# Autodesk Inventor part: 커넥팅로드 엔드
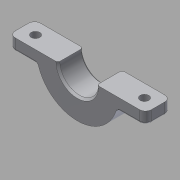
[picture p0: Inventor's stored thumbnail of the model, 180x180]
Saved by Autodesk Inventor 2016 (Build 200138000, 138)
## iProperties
Created: 2016-11
Part Number: 커넥팅로드 엔드
Material: 알루미늄 6061
Document SubType Name: Modeling
Designer: mduedu
Density: 2.71 g/cm^3
Mass: 24.1426 g
Surface Area: 36.9806 cm^2
Volume: 8.9087 cm^3
Appearance: 알루미늄 - 평지
Author: mduedu
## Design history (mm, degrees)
sketch "스케치1" dims "d0" = 42, "d3" = 20
  geometry: L1 (0, 0)-(0, 114); L2 (-7.5, 107.386)-(-12.5, 16.875); L3 (7.5, 107.386)-(12.5, 16.875); C1 r 10 at (0, 0); C2 r 6.5 at (0, 114); 3 further points
  constraints: 6 end point, 4 coincident, 2 centre point, 2 symmetric about line, 1 vertical, 6 other
  dimensions: "d1" = 20 diameter of C1; "d2" = 13 diameter of C2; "d4" = 114 distance of L1.start L1.end; "d6" = 12.5 distance from line of L1 L2.end; "d7" = 7.5 distance from line of L1 L2.start
extrude "돌출1" new body sketch "스케치1" stored distance "d8" = 13; taper "d9" = 0 deg
extrude "돌출2" join sketch "스케치1" stored distance "d10" = 20; taper "d11" = 0 deg
sketch "스케치2"
  geometry: L1 (-7.5, 107.386)-(-12.5, 16.875) reference; L2 (7.5, 107.386)-(12.5, 16.875) reference; A1 r 10 centre (0, 114) between (-7.5, 107.386) and (7.5, 107.386) reference; A2 r 21 centre (0, 0) between (-12.5, 16.875) and (12.5, 16.875) reference; 1 further point
extrude "돌출3" join sketch "스케치2" stored distance "d12" = 8; taper "d13" = 0 deg
sketch "스케치3"
  geometry: L1 (-7.5, 107.386)-(-12.5, 16.875) reference; L2 (7.5, 107.386)-(12.5, 16.875) reference; L3 (-4.209, 94.448)-(-7.768, 30.011); L4 (4.209, 94.448)-(7.768, 30.011); L5 (0, 94)-(0, 31); A1 r 10 centre (0, 114) between (-7.5, 107.386) and (7.5, 107.386) reference; A2 r 21 centre (0, 0) between (-12.5, 16.875) and (12.5, 16.875) reference; A3 r 20 centre (0, 114) between (-4.209, 94.448) and (4.209, 94.448); A4 r 31 centre (0, 0) between (7.768, 30.011) and (-7.768, 30.011); 1 further point
  constraints: 6 end point, 6 point on circle, 2 centre point, 2 parallel, 1 symmetric about line, 1 vertical alignment
  dimensions: "d18" = 10 radial gap between concentric circles of A3 A1; "d19" = 10 radial gap between concentric circles of A2 A4; "d20" = 4 distance between parallel lines of L3 L1
extrude "돌출4" cut sketch "스케치3" distance "d21" = 2; taper "d22" = 0 deg
fillet "모깎기1" dims "d23" = 3
fillet "모깎기2" dims "d24" = 2
fillet "모깎기3" dims "d25" = 2
chamfer "모따기1" distance "d26" = 1; stored, may be unused: second distance "d27" = 2, angle "d28" = 45 deg
sketch "스케치4"
  geometry: L1 (-35, -6)-(-20.125, -6); L2 (35, -6)-(35, 6); L3 (35, 6)-(20.125, 6); L4 (-35, 6)-(-35, -6); L5 (-35, -6)-(35, 6); L6 (35, -6)-(-35, 6); L7 (-20.125, 6)-(-35, 6); L8 (20.125, 6)-(-20.125, 6); L9 (20.125, -6)-(35, -6); L10 (-20.125, -6)-(20.125, -6); A1 r 21 centre (0, 0) between (-20.125, 6) and (20.125, 6) reference; 1 further point
  constraints: 20 end point, 10 parallel, 4 point on circle, 3 horizontal, 3 perpendicular, 2 midpoint
  dimensions: "d29" = 70 distance of L1.start L2.start; "d31" = 12 distance of L2.start L2.end
extrude "돌출5" join sketch "스케치4" stored distance "d32" = 0; taper "d33" = 0 deg
fillet "모깎기4" dims "d34" = 3
fillet "모깎기5" dims "d35" = 1
fillet "모깎기6" dims "d36" = 1
sketch "스케치5"
  geometry: L1 (1, 0)-(1, 7) reference; L2 (-24, 13.5)-(-44, 13.5) reference; L3 (-44, -6.5)-(-24, -6.5) reference; L4 (-34, 13.5)-(-34, -6.5); 3 further points
  constraints: 2 end point, 2 midpoint, 1 horizontal alignment, 1 symmetric about line
  dimensions: "d37" = 7 distance from line of point (-6, 3.5) L1
feature "분할1"
sketch "스케치6"
  geometry: 2 further points
  constraints: 2 other
hole "구멍1" sketch "스케치6" at (-62, 3.5), (-6, 3.5) diameter "d38" = 4.5; stored, may be unused: countersink angle "d42" = 90 deg, drill point angle "d44" = 0 deg; dims "d39" = 6, "d40" = 4, "d41" = 2, "d43" = 8
node "솔리드1"
mirror "대칭1"
other parameters: "d16" = 4, "d17" = 4
